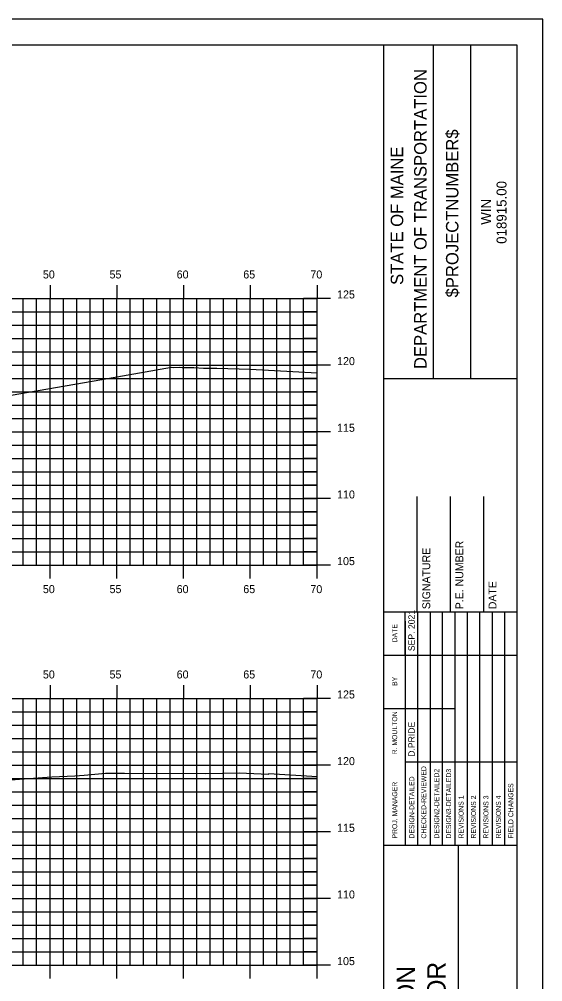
# Model space of a CAD drawing. Extents: x 853512 to 853684, y 365624 to 365734.
# Drawn here: x 853643.3 to 853682.5, y 365661.8 to 365734 of the extents above; entities that cross this region are included whole.
import ezdxf

# ---------------------------------------------------------------- set-up
doc = ezdxf.new("R2010")
doc.units = 0
for name, color, linetype in [('BORDER', 7, 'Continuous'), ('H_V ANNOTATION', 7, 'Continuous'), ('M_Roadway_Centerline', 7, 'Continuous'), ('MAJOR', 7, 'Continuous'), ('MINOR', 7, 'Continuous'), ('PLOT BOUNDARY', 7, 'Continuous'), ('S_Roadway_Centerline', 7, 'Continuous')]:
    doc.layers.add(name, color=color, linetype=linetype)

msp = doc.modelspace()

# ---------------------------------------------------------------- linework, layer by layer
at = {"layer": 'BORDER'}
for p, q in [((853670.575, 365627.027), (853670.575, 365732.027)), ((853674.303, 365707.024), (853674.303, 365732.024)), ((853677.098, 365707.024), (853677.098, 365732.024)), ((853670.576, 365707.021), (853680.575, 365707.021)), ((853673.075, 365689.53), (853673.075, 365698.177)), ((853675.575, 365689.53), (853675.575, 365698.177)), ((853678.075, 365689.53), (853678.075, 365698.177)), ((853670.575, 365689.53), (853680.575, 365689.53)), ((853670.575, 365672.03), (853680.575, 365672.03)), ((853676.166, 365637.03), (853676.166, 365672.03))]:
    msp.add_line(p, q, dxfattribs=at)
msp.add_lwpolyline([(853520.575, 365627.027), (853680.575, 365627.027), (853680.575, 365732.027), (853520.575, 365732.027)], close=True, dxfattribs=at)
for points in [[(853672.19, 365686.28), (853672.19, 365689.53)], [(853673.122, 365672.033), (853673.122, 365689.53)], [(853674.054, 365689.53), (853674.054, 365672.033)], [(853674.986, 365672.033), (853674.986, 365689.53)], [(853675.917, 365672.033), (853675.917, 365689.53)], [(853676.849, 365672.033), (853676.849, 365689.53)], [(853677.781, 365672.033), (853677.781, 365689.53)], [(853678.712, 365672.033), (853678.712, 365689.53)], [(853679.644, 365672.033), (853679.644, 365689.53)], [(853672.191, 365672.033), (853672.191, 365688.824)], [(853670.575, 365686.28), (853680.575, 365686.28)], [(853670.575, 365682.28), (853672.191, 365682.28)], [(853672.19, 365682.28), (853675.916, 365682.28)], [(853672.19, 365678.28), (853680.575, 365678.28)]]:
    msp.add_lwpolyline(points, dxfattribs=at)
at = {"layer": 'MAJOR'}
for p, q in [((853645.575, 365714.029), (853645.575, 365713.027)), ((853650.575, 365714.029), (853650.575, 365713.027)), ((853655.575, 365714.029), (853655.575, 365713.027)), ((853660.575, 365714.029), (853660.575, 365713.027)), ((853665.575, 365714.029), (853665.575, 365713.027)), ((853525.575, 365713.027), (853665.575, 365713.027)), ((853525.575, 365713.027), (853665.575, 365713.027)), ((853645.575, 365693.027), (853645.575, 365713.027)), ((853650.575, 365693.027), (853650.575, 365713.027)), ((853655.575, 365693.027), (853655.575, 365713.027)), ((853660.575, 365693.027), (853660.575, 365713.027)), ((853666.577, 365713.027), (853664.573, 365713.027)), ((853665.575, 365693.027), (853665.575, 365713.027)), ((853665.575, 365693.027), (853665.575, 365713.027)), ((853525.575, 365708.027), (853665.575, 365708.027)), ((853666.577, 365708.027), (853664.573, 365708.027)), ((853525.575, 365703.027), (853665.575, 365703.027)), ((853666.577, 365703.027), (853664.573, 365703.027)), ((853525.575, 365698.027), (853665.575, 365698.027)), ((853666.577, 365698.027), (853664.573, 365698.027)), ((853525.575, 365693.027), (853665.575, 365693.027)), ((853525.575, 365693.027), (853665.575, 365693.027)), ((853645.575, 365692.025), (853645.575, 365693.027)), ((853650.575, 365692.025), (853650.575, 365693.027)), ((853655.575, 365692.025), (853655.575, 365693.027)), ((853660.575, 365692.025), (853660.575, 365693.027)), ((853666.577, 365693.027), (853664.573, 365693.027)), ((853665.575, 365692.025), (853665.575, 365693.027)), ((853645.575, 365684.029), (853645.575, 365683.027)), ((853650.575, 365684.029), (853650.575, 365683.027)), ((853655.575, 365684.029), (853655.575, 365683.027)), ((853660.575, 365684.029), (853660.575, 365683.027)), ((853665.575, 365684.029), (853665.575, 365683.027)), ((853525.575, 365683.027), (853665.575, 365683.027)), ((853525.575, 365683.027), (853665.575, 365683.027)), ((853645.575, 365663.027), (853645.575, 365683.027)), ((853650.575, 365663.027), (853650.575, 365683.027)), ((853655.575, 365663.027), (853655.575, 365683.027)), ((853660.575, 365663.027), (853660.575, 365683.027)), ((853666.577, 365683.027), (853664.573, 365683.027)), ((853665.575, 365663.027), (853665.575, 365683.027)), ((853665.575, 365663.027), (853665.575, 365683.027)), ((853525.575, 365678.027), (853665.575, 365678.027)), ((853666.577, 365678.027), (853664.573, 365678.027)), ((853525.575, 365673.027), (853665.575, 365673.027)), ((853666.577, 365673.027), (853664.573, 365673.027)), ((853525.575, 365668.027), (853665.575, 365668.027)), ((853666.577, 365668.027), (853664.573, 365668.027)), ((853525.575, 365663.027), (853665.575, 365663.027)), ((853525.575, 365663.027), (853665.575, 365663.027)), ((853645.575, 365662.025), (853645.575, 365663.027)), ((853650.575, 365662.025), (853650.575, 365663.027)), ((853655.575, 365662.025), (853655.575, 365663.027)), ((853660.575, 365662.025), (853660.575, 365663.027)), ((853666.577, 365663.027), (853664.573, 365663.027)), ((853665.575, 365662.025), (853665.575, 365663.027))]:
    msp.add_line(p, q, dxfattribs=at)
at = {"layer": 'MINOR'}
for p, q in [((853643.575, 365693.027), (853643.575, 365713.027)), ((853644.575, 365693.027), (853644.575, 365713.027)), ((853646.575, 365693.027), (853646.575, 365713.027)), ((853647.575, 365693.027), (853647.575, 365713.027)), ((853648.575, 365693.027), (853648.575, 365713.027)), ((853649.575, 365693.027), (853649.575, 365713.027)), ((853651.575, 365693.027), (853651.575, 365713.027)), ((853652.575, 365693.027), (853652.575, 365713.027)), ((853653.575, 365693.027), (853653.575, 365713.027)), ((853654.575, 365693.027), (853654.575, 365713.027)), ((853656.575, 365693.027), (853656.575, 365713.027)), ((853657.575, 365693.027), (853657.575, 365713.027)), ((853658.575, 365693.027), (853658.575, 365713.027)), ((853659.575, 365693.027), (853659.575, 365713.027)), ((853661.575, 365693.027), (853661.575, 365713.027)), ((853662.575, 365693.027), (853662.575, 365713.027)), ((853663.575, 365693.027), (853663.575, 365713.027)), ((853664.575, 365693.027), (853664.575, 365713.027)), ((853525.575, 365712.027), (853665.575, 365712.027)), ((853665.575, 365712.027), (853664.573, 365712.027)), ((853525.575, 365711.027), (853665.575, 365711.027)), ((853665.575, 365711.027), (853664.573, 365711.027)), ((853525.575, 365710.027), (853665.575, 365710.027)), ((853665.575, 365710.027), (853664.573, 365710.027)), ((853525.575, 365709.027), (853665.575, 365709.027)), ((853665.575, 365709.027), (853664.573, 365709.027)), ((853525.575, 365707.027), (853665.575, 365707.027)), ((853665.575, 365707.027), (853664.573, 365707.027)), ((853525.575, 365706.027), (853665.575, 365706.027)), ((853665.575, 365706.027), (853664.573, 365706.027)), ((853525.575, 365705.027), (853665.575, 365705.027)), ((853665.575, 365705.027), (853664.573, 365705.027)), ((853525.575, 365704.027), (853665.575, 365704.027)), ((853665.575, 365704.027), (853664.573, 365704.027)), ((853525.575, 365702.027), (853665.575, 365702.027)), ((853665.575, 365702.027), (853664.573, 365702.027)), ((853525.575, 365701.027), (853665.575, 365701.027)), ((853665.575, 365701.027), (853664.573, 365701.027)), ((853525.575, 365700.027), (853665.575, 365700.027)), ((853665.575, 365700.027), (853664.573, 365700.027)), ((853525.575, 365699.027), (853665.575, 365699.027)), ((853665.575, 365699.027), (853664.573, 365699.027)), ((853525.575, 365697.027), (853665.575, 365697.027)), ((853665.575, 365697.027), (853664.573, 365697.027)), ((853525.575, 365696.027), (853665.575, 365696.027)), ((853665.575, 365696.027), (853664.573, 365696.027)), ((853525.575, 365695.027), (853665.575, 365695.027)), ((853665.575, 365695.027), (853664.573, 365695.027)), ((853525.575, 365694.027), (853665.575, 365694.027)), ((853665.575, 365694.027), (853664.573, 365694.027)), ((853643.575, 365663.027), (853643.575, 365683.027)), ((853644.575, 365663.027), (853644.575, 365683.027)), ((853646.575, 365663.027), (853646.575, 365683.027)), ((853647.575, 365663.027), (853647.575, 365683.027)), ((853648.575, 365663.027), (853648.575, 365683.027)), ((853649.575, 365663.027), (853649.575, 365683.027)), ((853651.575, 365663.027), (853651.575, 365683.027)), ((853652.575, 365663.027), (853652.575, 365683.027)), ((853653.575, 365663.027), (853653.575, 365683.027)), ((853654.575, 365663.027), (853654.575, 365683.027)), ((853656.575, 365663.027), (853656.575, 365683.027)), ((853657.575, 365663.027), (853657.575, 365683.027)), ((853658.575, 365663.027), (853658.575, 365683.027)), ((853659.575, 365663.027), (853659.575, 365683.027)), ((853661.575, 365663.027), (853661.575, 365683.027)), ((853662.575, 365663.027), (853662.575, 365683.027)), ((853663.575, 365663.027), (853663.575, 365683.027)), ((853664.575, 365663.027), (853664.575, 365683.027)), ((853525.575, 365682.027), (853665.575, 365682.027)), ((853665.575, 365682.027), (853664.573, 365682.027)), ((853525.575, 365681.027), (853665.575, 365681.027)), ((853665.575, 365681.027), (853664.573, 365681.027)), ((853525.575, 365680.027), (853665.575, 365680.027)), ((853665.575, 365680.027), (853664.573, 365680.027)), ((853525.575, 365679.027), (853665.575, 365679.027)), ((853665.575, 365679.027), (853664.573, 365679.027)), ((853525.575, 365677.027), (853665.575, 365677.027)), ((853665.575, 365677.027), (853664.573, 365677.027)), ((853525.575, 365676.027), (853665.575, 365676.027)), ((853665.575, 365676.027), (853664.573, 365676.027)), ((853525.575, 365675.027), (853665.575, 365675.027)), ((853665.575, 365675.027), (853664.573, 365675.027)), ((853525.575, 365674.027), (853665.575, 365674.027)), ((853665.575, 365674.027), (853664.573, 365674.027)), ((853525.575, 365672.027), (853665.575, 365672.027)), ((853665.575, 365672.027), (853664.573, 365672.027)), ((853525.575, 365671.027), (853665.575, 365671.027)), ((853665.575, 365671.027), (853664.573, 365671.027)), ((853525.575, 365670.027), (853665.575, 365670.027)), ((853665.575, 365670.027), (853664.573, 365670.027)), ((853525.575, 365669.027), (853665.575, 365669.027)), ((853665.575, 365669.027), (853664.573, 365669.027)), ((853525.575, 365667.027), (853665.575, 365667.027)), ((853665.575, 365667.027), (853664.573, 365667.027)), ((853525.575, 365666.027), (853665.575, 365666.027)), ((853665.575, 365666.027), (853664.573, 365666.027)), ((853525.575, 365665.027), (853665.575, 365665.027)), ((853665.575, 365665.027), (853664.573, 365665.027)), ((853525.575, 365664.027), (853665.575, 365664.027)), ((853665.575, 365664.027), (853664.573, 365664.027))]:
    msp.add_line(p, q, dxfattribs=at)
at = {"layer": 'PLOT BOUNDARY'}
msp.add_lwpolyline([(853512.481, 365623.968), (853682.481, 365623.968), (853682.481, 365733.968), (853512.481, 365733.968)], close=True, dxfattribs=at)
at = {"layer": 'S_Roadway_Centerline'}
for points in [[(853584.159, 365706.037), (853593.037, 365706.394), (853595.213, 365706.498), (853600.208, 365706.521), (853603.056, 365706.435), (853611.204, 365706.146), (853612.332, 365705.938), (853619.285, 365704.571), (853626.269, 365703.743), (853628.823, 365703.496), (853633.667, 365704.187), (853637.151, 365704.825), (853649.447, 365706.952), (853654.675, 365707.863), (853654.79, 365707.86), (853655.281, 365707.863), (853655.479, 365707.86), (853656.357, 365707.841), (853657.066, 365707.809), (853658.062, 365707.803), (853660.567, 365707.714), (853665.575, 365707.438)], [(853589.415, 365676.405), (853599.207, 365676.766), (853599.921, 365676.825), (853600.862, 365676.773), (853602.595, 365676.77), (853606.652, 365676.743), (853615.951, 365676.647), (853617.308, 365676.575), (853621.165, 365676.549), (853624.969, 365676.485), (853635.352, 365676.394), (853645.716, 365677.143), (853647.446, 365677.228), (853648.142, 365677.273), (853649.721, 365677.423), (853651.167, 365677.428), (853657.245, 365677.407), (853659.739, 365677.437), (853661.931, 365677.354), (853661.978, 365677.397), (853665.575, 365677.181)]]:
    msp.add_lwpolyline(points, dxfattribs=at)

# ---------------------------------------------------------------- texts
at = {"layer": 'BORDER'}
for s, height, p in [('DEPARTMENT OF TRANSPORTATION', 0.93176, (853673.782, 365707.733)), ('$PROJECTNUMBER$', 0.93176, (853676.167, 365713.106)), ('STATE OF MAINE', 0.93176, (853672.03, 365714.039)), ('018915.00', 0.7453, (853679.77, 365717.125)), ('WIN', 0.7453, (853678.612, 365718.557)), ('P.E. NUMBER', 0.59055, (853676.536, 365689.722)), ('SIGNATURE', 0.5906, (853674.055, 365689.722)), ('DATE', 0.5906, (853679.016, 365689.722)), ('SEP. 2021', 0.4845, (853672.897, 365686.575)), ('DATE', 0.3714, (853671.579, 365687.235)), ('BY', 0.3714, (853671.579, 365683.965)), ('R. MOULTON', 0.3727, (853671.578, 365678.832)), ('D.PRIDE', 0.4845, (853672.897, 365678.653)), ('CHECKED-REVIEWED', 0.37275, (853673.756, 365672.518)), ('DESIGN2-DETAILED2', 0.37275, (853674.725, 365672.518)), ('DESIGN3-DETAILED3', 0.37275, (853675.619, 365672.518)), ('DESIGN-DETAILED', 0.37275, (853672.861, 365672.518)), ('PROJ. MANAGER', 0.37275, (853671.579, 365672.518)), ('FIELD CHANGES', 0.37275, (853680.278, 365672.518)), ('REVISIONS 1', 0.37275, (853676.551, 365672.518)), ('REVISIONS 2', 0.37275, (853677.483, 365672.518)), ('REVISIONS 3', 0.37275, (853678.414, 365672.518)), ('REVISIONS 4', 0.37275, (853679.346, 365672.518)), ('I-395/ROUTE 9 CONNECTOR', 1.37787, (853675.209, 365638.192)), ('BREWER TO EDDINGTON', 1.37787, (853672.908, 365640.231))]:
    msp.add_text(s, height=height, rotation=90, dxfattribs=at).set_placement(p)
at = {"layer": 'H_V ANNOTATION'}
for s, p in [('50', (853645.039, 365714.527)), ('55', (853650.031, 365714.527)), ('60', (853655.061, 365714.527)), ('65', (853660.053, 365714.527)), ('70', (853665.077, 365714.527)), ('125', (853667.075, 365713.027)), ('120', (853667.075, 365708.027)), ('115', (853667.075, 365703.027)), ('110', (853667.075, 365698.027)), ('105', (853667.075, 365693.027)), ('50', (853645.039, 365690.927)), ('55', (853650.031, 365690.927)), ('60', (853655.061, 365690.927)), ('65', (853660.053, 365690.927)), ('70', (853665.077, 365690.927)), ('50', (853645.039, 365684.527)), ('55', (853650.031, 365684.527)), ('60', (853655.061, 365684.527)), ('65', (853660.053, 365684.527)), ('70', (853665.077, 365684.527)), ('125', (853667.075, 365683.027)), ('120', (853667.075, 365678.027)), ('115', (853667.075, 365673.027)), ('110', (853667.075, 365668.027)), ('105', (853667.075, 365663.027))]:
    msp.add_text(s, height=0.6, dxfattribs=at).set_placement(p)
at = {"layer": 'M_Roadway_Centerline'}
for s, p in [('C', (853661.973, 365677.397)), ('L', (853661.978, 365677.389))]:
    msp.add_text(s, height=0.0146, dxfattribs=at).set_placement(p)

doc.saveas('drawing.dxf')
